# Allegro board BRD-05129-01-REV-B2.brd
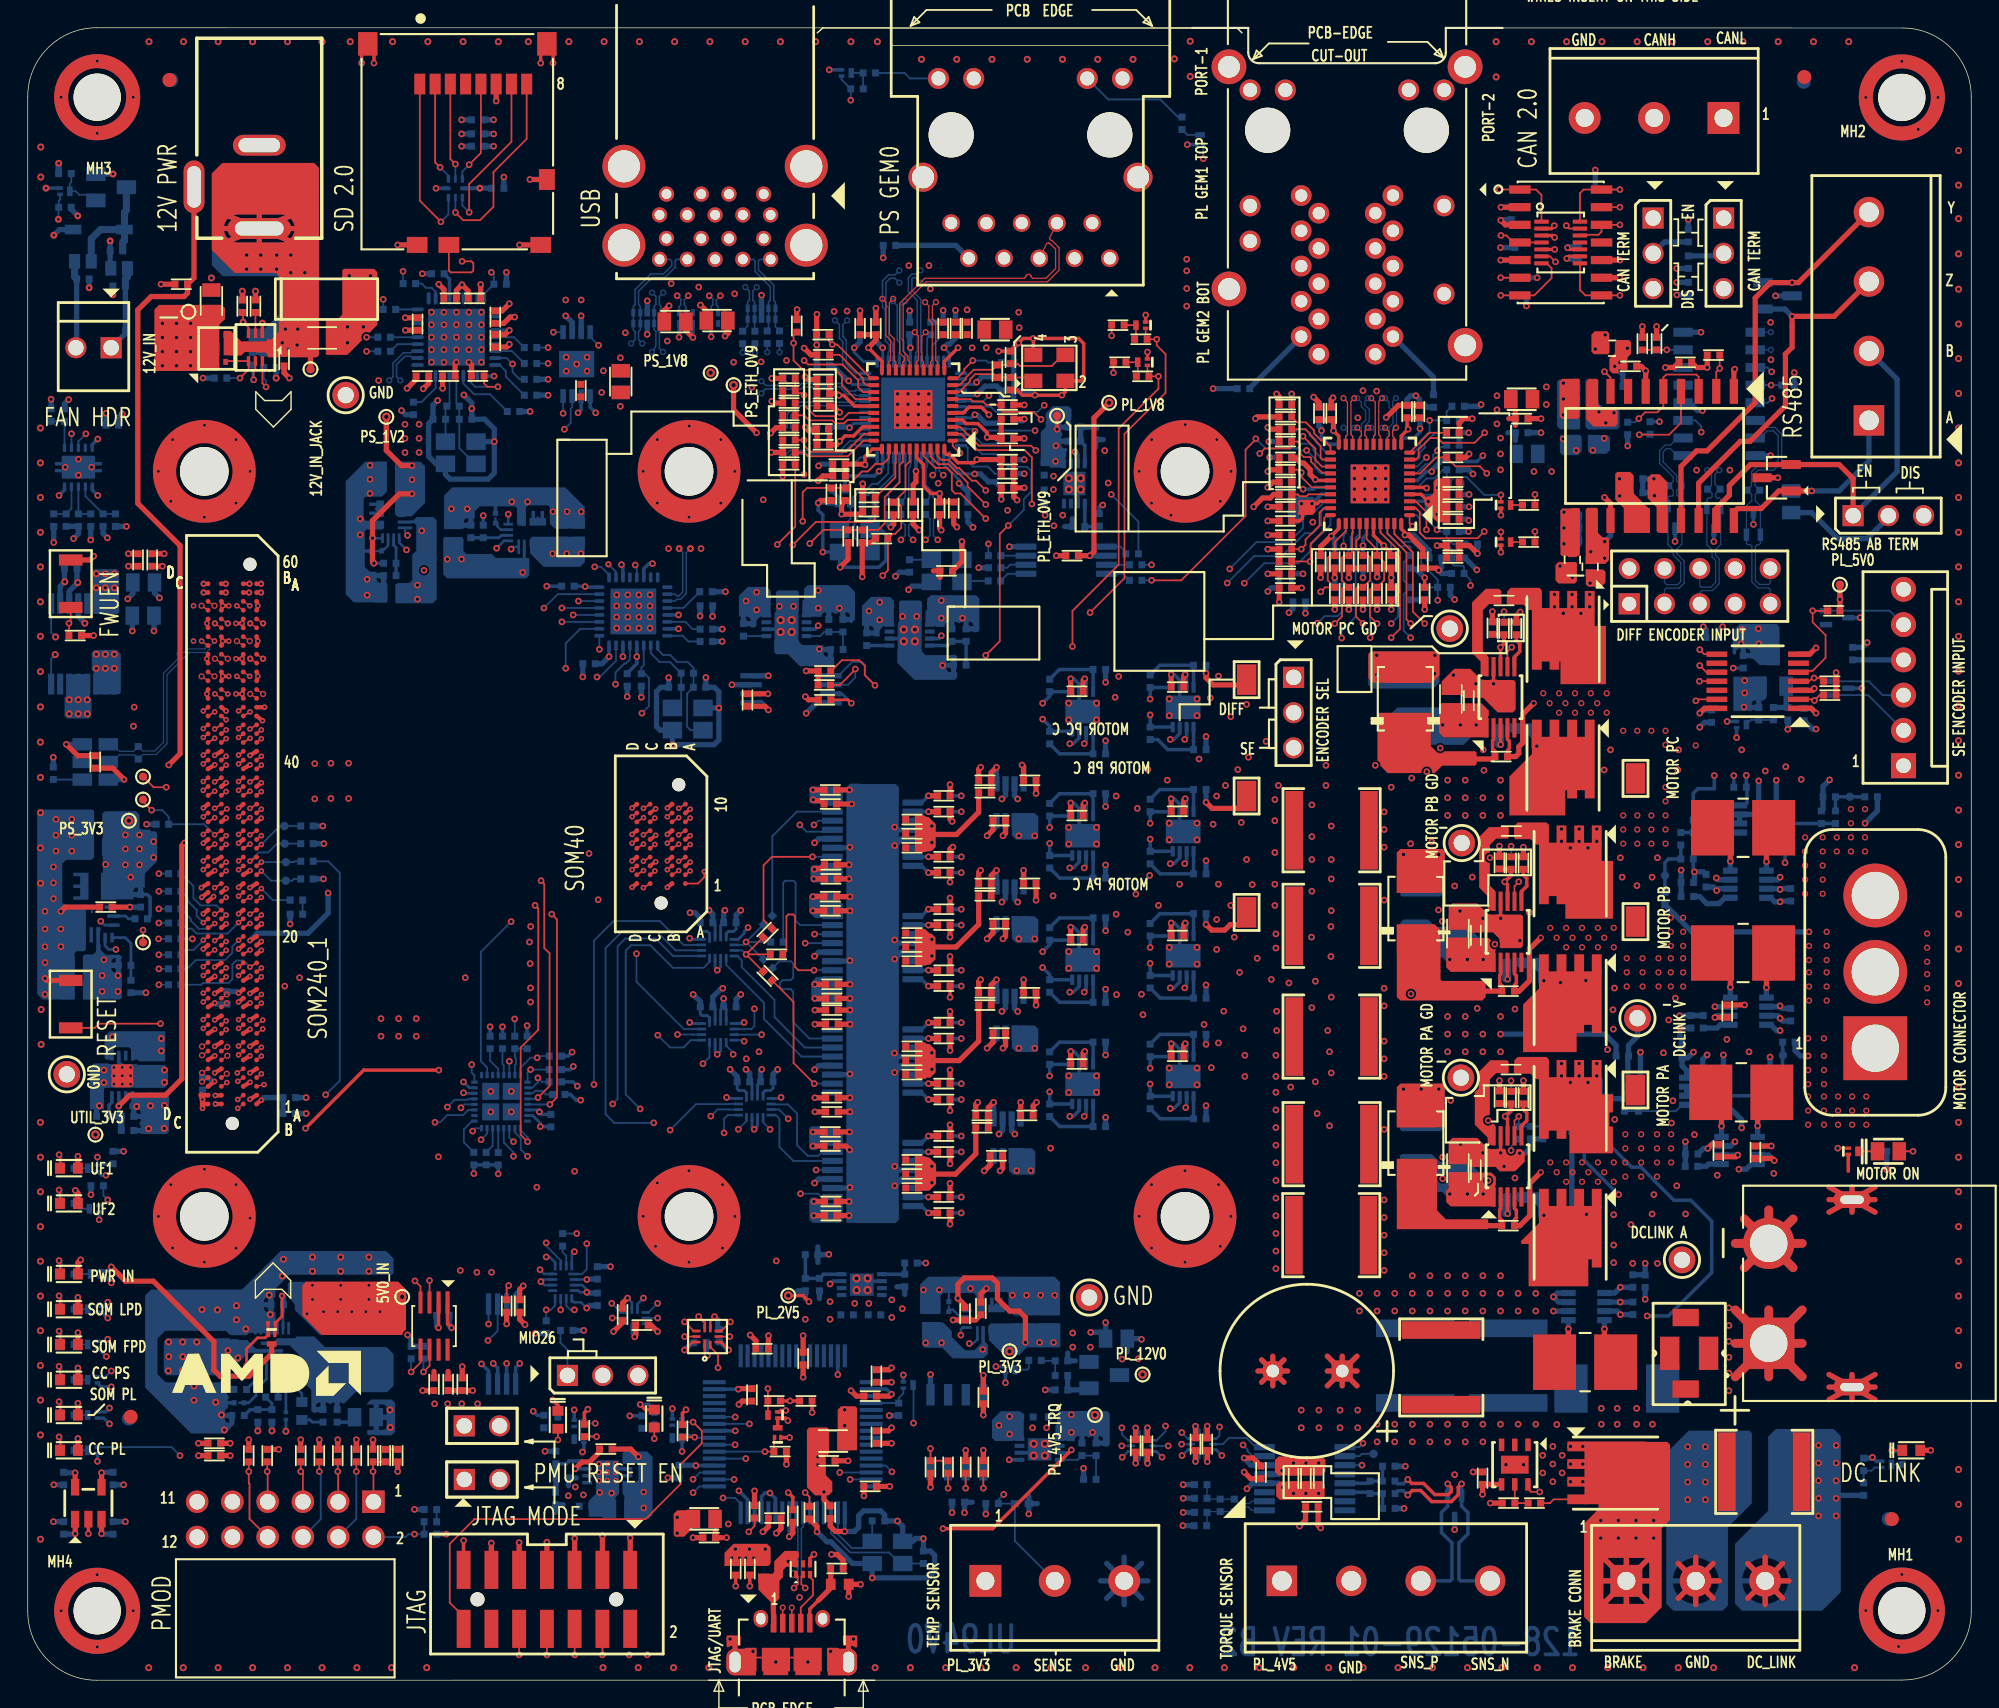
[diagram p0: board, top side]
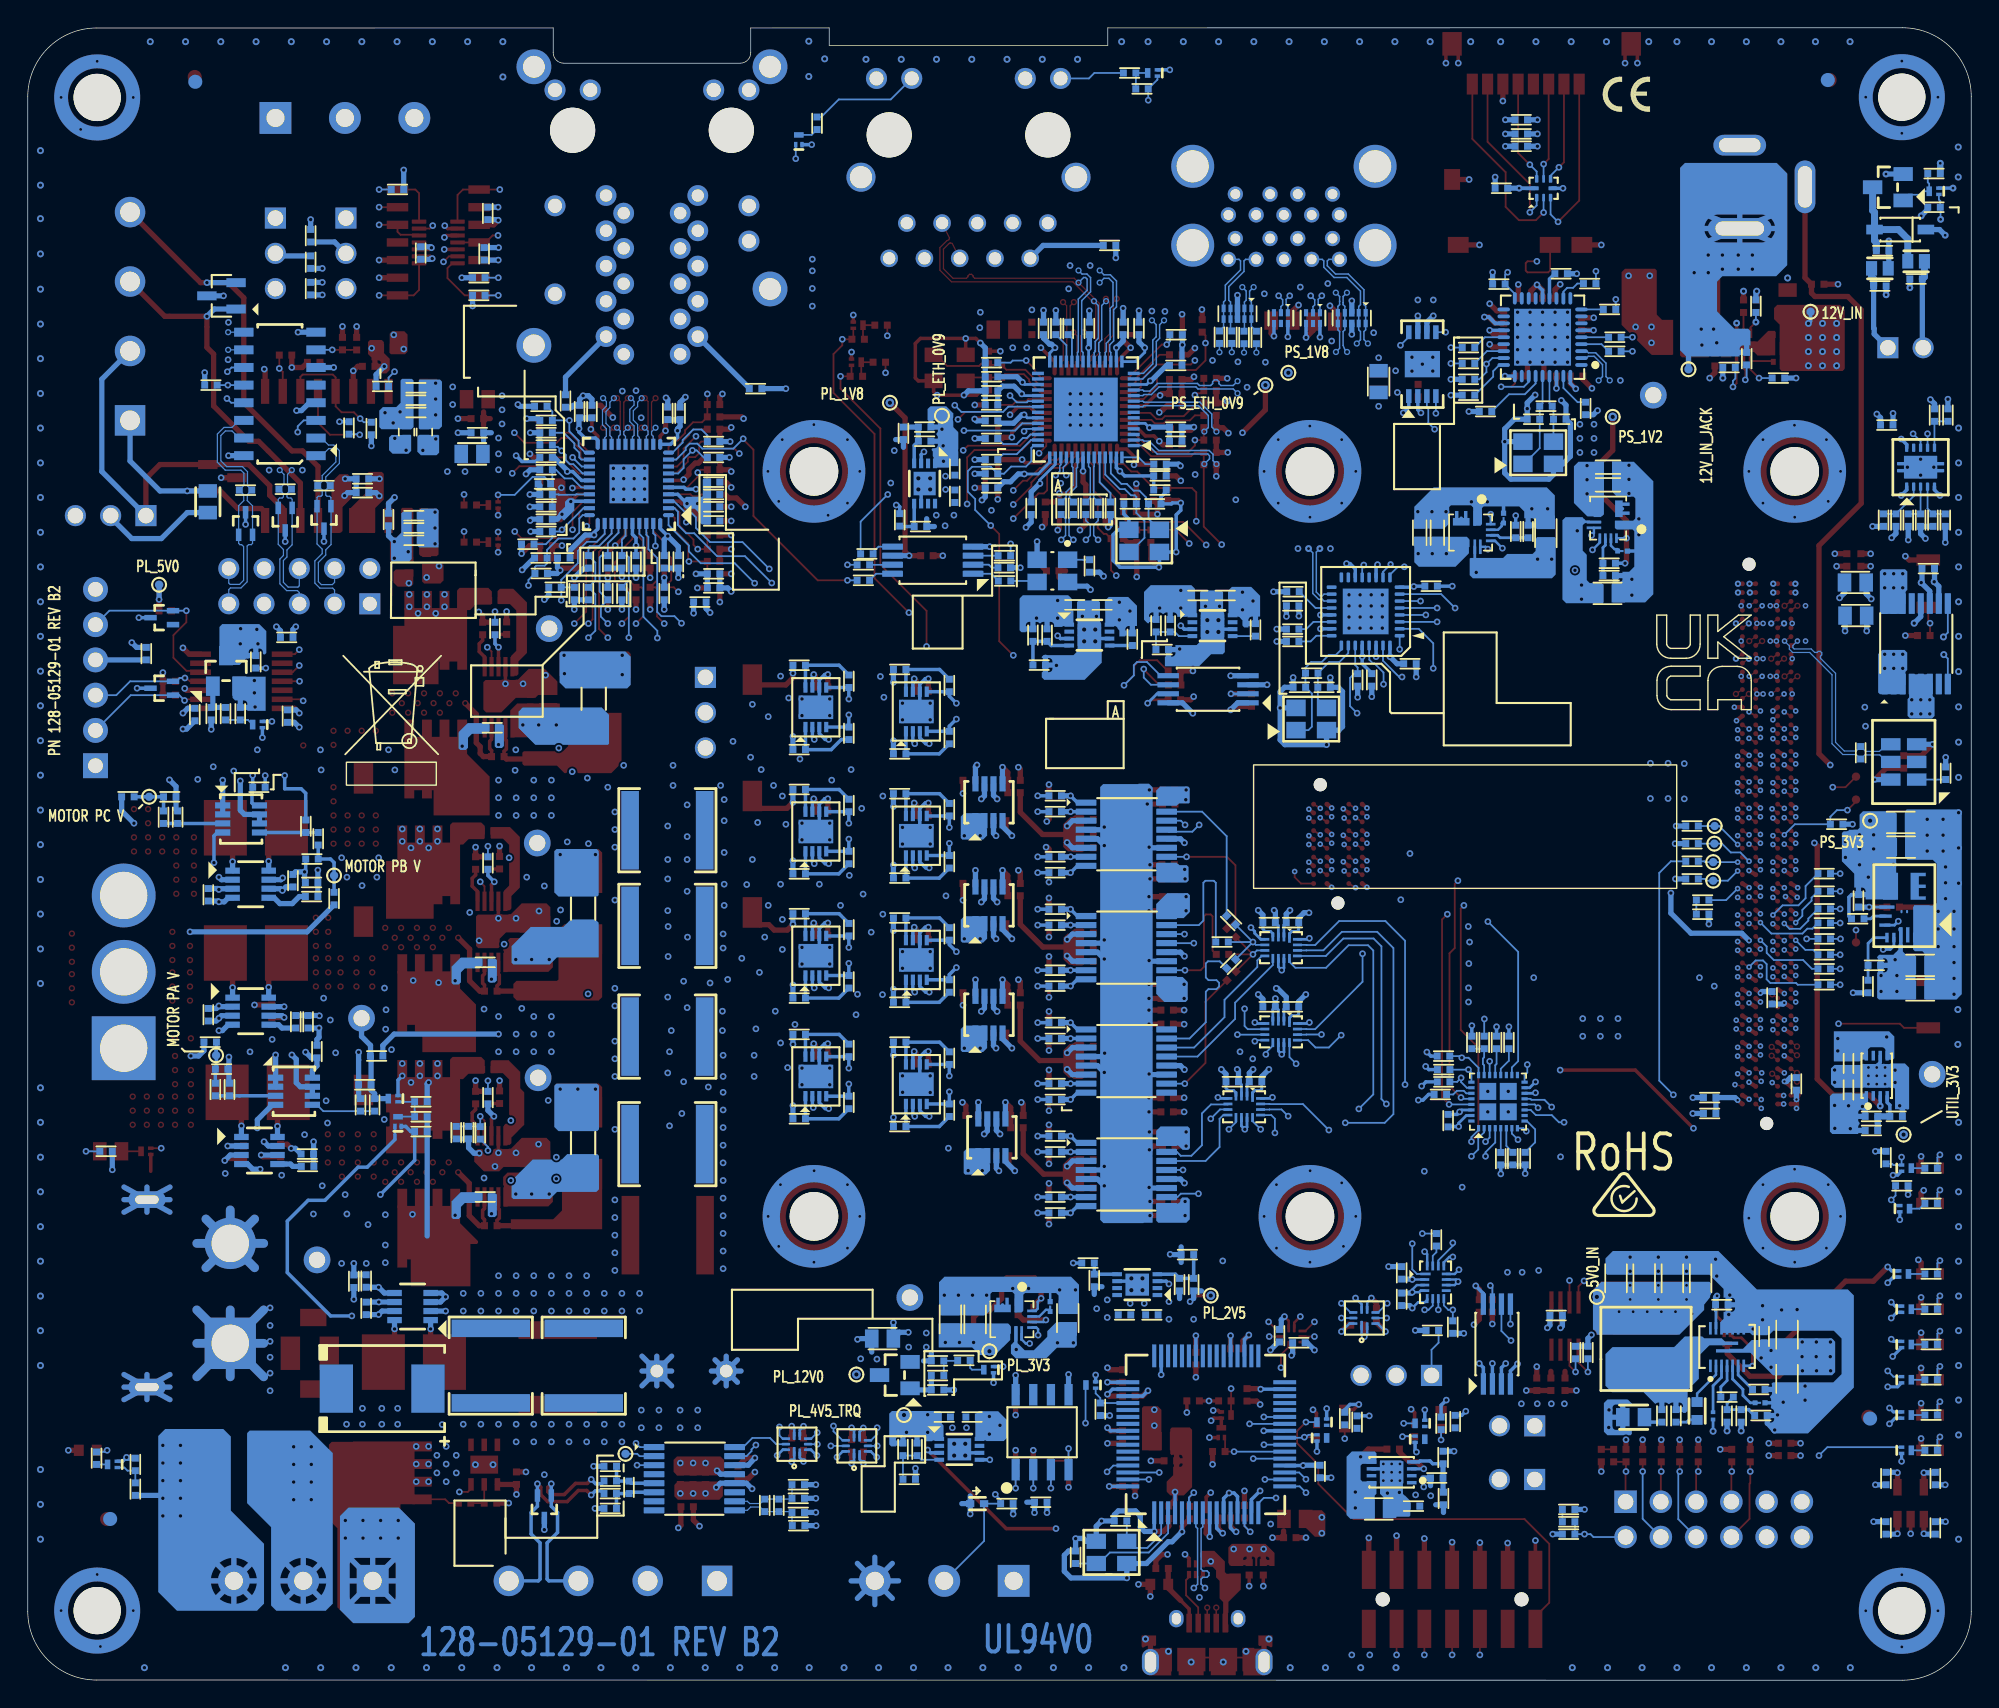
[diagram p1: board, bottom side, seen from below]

Outline 140 x 119 mm; copper layers: TOP, L02_GND, L03_SIG, L04_GND, L05_SIG, L06_GND, L07_PWR, L08_PWR, L09_GND, L10_SIG, L11_GND, L12_SIG, L13_GND, BOTTOM. Coordinates in mm from the lower left corner of the outline.
Outline path: 0,114.05 0,4.95 arc(1.45,1.45) 4.95,0 135.05,0.01 arc(138.55,1.47) 140,4.97 140,114.03 arc(138.55,117.53) 135.05,118.98 102.15,118.99 102.15,117.21 arc(101.93,116.67) 101.39,116.45 88.68,116.45 arc(88.14,116.67) 87.92,117.21 87.92,118.99 82.27,118.99 82.27,117.72 62.2,117.72 62.2,118.99 4.95,119 arc(1.45,117.55) 0,114.05

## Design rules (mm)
constraint set DEFAULT: min track width 0.13
net group 000-GTH_GTR_NC: nets GTR_DP1_C2M_N_NC GTR_DP1_C2M_P_NC
net group 23-PMOD_1-2_HD_SIGNALS: nets HDA08_CC HDA09_NC
net group GEM_SGMII_SO: nets GTR_DP0_C2M_N_NC GTR_DP0_C2M_P_NC
net group GTR_DP0_M2C_PAIR: nets GTR_DP0_M2C_N_NC GTR_DP0_M2C_P_NC
net group GTR_DP1_M2C_PAIR: nets GTR_DP1_M2C_N_NC GTR_DP1_M2C_P_NC
net group GTR_DP3_C2M: nets GTR_DP3_C2M_N_NC GTR_DP3_C2M_P_NC
net group GTR_DP3_M2C: nets GTR_DP3_M2C_N_NC GTR_DP3_M2C_P_NC
net group GTR_REFCLK0_C2M_PAIR: nets GTR_REFCLK0_C2M_N_NC GTR_REFCLK0_C2M_P_NC
net group GTR_REFCLK1_C2M_PAIR: nets GTR_REFCLK1_C2M_N_NC GTR_REFCLK1_C2M_P_NC
net group HDA12: nets HDA12 PMOD1_IO2_HDA12
net group HDA13: nets HDA13 PMOD1_IO3_HDA13
net group HDA14: nets HDA14 PMOD1_IO4_HDA14
net group HDA16_CC: nets HDA16_CC PMOD1_IO6_HDA16_CC
net group HDA17: nets HDA17 PMOD1_IO7_HDA17
net group HDA18: nets HDA18 PMOD1_IO8_HDA18
net group MG1_ETHERNET_GEM0_RGMII: nets MIO50 MIO51
net group MG7_MIO_RS485: nets MIO71 MIO72
net group MODE1_C2M: nets MODE1_C2M N15991161
net group N16080552: nets N16080552 N16080556
net group N16080656: nets N16080656 N16080660
net group N16080760: nets N16080760 N16080764
net group N16080864: nets N16080864 N16080868
net group N16080968: nets N16080968 N16080972
net group N16081072: nets N16081072 N16081076
net group N16082050: nets N16082024 N16082050
net group PL_GEM1_MDI_0: nets PL_GEM1_MDI_0_N PL_GEM1_MDI_0_P
net group PL_GEM1_MDI_1: nets PL_GEM1_MDI_1_N PL_GEM1_MDI_1_P
net group PL_GEM1_MDI_2: nets PL_GEM1_MDI_2_N PL_GEM1_MDI_2_P
net group PL_GEM1_MDI_3: nets PL_GEM1_MDI_3_N PL_GEM1_MDI_3_P
net group PL_GEM2_MDI_0: nets PL_GEM2_MDI_0_N PL_GEM2_MDI_0_P
net group PL_GEM2_MDI_1: nets PL_GEM2_MDI_1_N PL_GEM2_MDI_1_P
net group PL_GEM2_MDI_2: nets PL_GEM2_MDI_2_N PL_GEM2_MDI_2_P
net group PL_GEM2_MDI_3: nets PL_GEM2_MDI_3_N PL_GEM2_MDI_3_P
net group PS_GEM0_MDI_0: nets PS_GEM0_MDI_0_N PS_GEM0_MDI_0_P
net group PS_GEM0_MDI_1: nets PS_GEM0_MDI_1_N PS_GEM0_MDI_1_P
net group PS_GEM0_MDI_2: nets PS_GEM0_MDI_2_N PS_GEM0_MDI_2_P
net group PS_GEM0_MDI_3: nets PS_GEM0_MDI_3_N PS_GEM0_MDI_3_P
net group QEI_DP_A: nets QEI_DP_A_N QEI_DP_A_P
net group QEI_DP_B: nets QEI_DP_B_N QEI_DP_B_P
net group QEI_DP_I: nets QEI_DP_I_N QEI_DP_I_P
net group SDIO_CLK: nets SDIO_CLK SDIO_CLK_R
net group SDIO_CMD: nets SDIO_CMD SDIO_CMD_R
net group SDIO_DATA0: nets SDIO_DATA0 SDIO_DATA0_R
net group SDIO_DATA1: nets SDIO_DATA1 SDIO_DATA1_R
net group SDIO_DATA2: nets SDIO_DATA2 SDIO_DATA2_R
net group SDIO_DATA3: nets SDIO_DATA3 SDIO_DATA3_R
net group TRQ_REFIN: nets TRQ_REFIN_N TRQ_REFIN_P
net group TRQ_SNS: nets TRQ_SNS_N TRQ_SNS_P
net group TRQ_SNS_R: nets TRQ_SNS_R_N TRQ_SNS_R_P
net group 000-MIO_NC_SIGNALS: nets MIO32_NC MIO33_NC MIO34_NC
net group 1-SFP_HD_SIGNALS: nets HDA19_NC
net group 10-GEM2_HP_SIGNALS: nets HPA07P_CLK
net group 17-USB1_MIO_SIGNALS: nets MIO64_NC MIO65_NC MIO69_NC MIO73_NC MIO74_NC MIO75_NC
net group 22-DISPLAY_PORT_MIO: nets MIO27_NC MIO28_NC MIO29_NC MIO30_NC
net group 30-EEPROM_HD_SIGNALS: nets HDA01_NC
net group 33-PWR_GND: nets 5V0_IN_VCC 12V_FAN_GND 12V_FAN_PWR AGND1 AGND2 AGND3 AGND4 DCLINK_VOLT MOTOR_PA_VOLT MOTOR_PB_VOLT MOTOR_PB_VOLTAGE+ MOTOR_PB_VOLTAGE- MOTOR_PC_VOLT N5304511 N5322338 N5327477 N15992479 N15992497 N15992515 PL_4V5_TRQ PMOD_PWR_FLT_B VCC_BATT VCCOEN_PL_M2C VCCOEN_PS_M2C VREF_DCLINK VREF_PA VREF_PB VREF_PC
net group FTDI_NETS: nets FTDI_LS_OE_B FTDI_PS_POR_B FTDI_PS_SRST_B FTDI_TCK FTDI_TDI FTDI_TDO FTDI_TMS FTDI_UARTB_RXD FTDI_UARTB_TXD
net group GEM0_ETH_RX_RGMII_BUS: nets HPA09P HPA11P_CLK HPA_CLK0P_CLK
net group HDA11: nets HDA11
net group HDA15: nets HDA15
net group JTAG_TCK_C2M: nets JTAG_TCK_C2M N2549814 N16081750
net group JUNK: nets N3957555 N3957585 N3957595 N16082016 N16082026 N16082028 N16082060 N16082074 N16082098
net group MG2-ETHERNET_GEM1_RGMII: nets HPA05_CCN HPA05_CCP HPA06P HPA09N HPA10_CCN HPA10_CCP_CLK HPA_CLK0N
net group MG3-ETHERNET_GEM2_RGMII: nets HPA15_CCN HPA15_CCP HPA16N HPA16P_CLK HPA17N HPA18N HPA18P HPA19N HPA19P HPA20_CCP_CLK HPA22N HPA22P HPA24N HPA24P
net group MG5-SDIO_SIGNALS: nets SDIO_CD_B
net group MG6-USB0_MIO_SIGNALS: nets MIO52 MIO53 MIO54 MIO55 MIO56 MIO57 MIO58 MIO59 MIO60 MIO61 MIO62 MIO63
net group MG_MIO_CAN2.0: nets MIO66 MIO67 MIO68
net group MOTOR_PA_CS_B: nets MOTOR_CS_B_R MOTOR_PA_CS_B MOTOR_PB_CS_B MOTOR_PC_CS_B
net group MOTOR_PA_SCLK: nets MOTOR_PA_SCLK MOTOR_PB_SCLK MOTOR_PC_SCLK MOTOR_SCLK_R
net group PL_2V5_FB: nets PL_2V5_FB
net group POWER: nets N16081820
net group SDIO_CARD_BUS: nets SDIO_SCK SDIO_SDA SDIO_WP
net group USB_JTAG_VBUS: nets N16081954
net group WATCHDOG_NETS: nets WATCHDOG_CRST WATCHDOG_CWD WATCHDOG_SET0 WATCHDOG_SET1 WATCHDOG_WDO_B

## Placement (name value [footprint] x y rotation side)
C1  22UF  [CAPC200X125X145]  5.05 60 180 bottom
C2  22UF  [CAPC200X125X145]  5.08 61.77 180 bottom
C3  22UF  [CAPC200X125X145]  3.68 51.48 180 bottom
C4  47UF  [CAPC200X125X125]  3.68 49.7 180 bottom
C5  27PF  [CAPC100X50X55]  8.17 54.83 180 bottom
C6  22UF  [CAPC200X125X145]  30.64 82.6 90 bottom
C7  22UF  [CAPC160X80X100]  39.73 82.64 90 bottom
C8  22UF  [CAPC160X80X100]  38.46 82.64 90 bottom
C14  1000PF  [CAPC100X50X55]  66.58 75.26 270 bottom
C16  10UF  [CAPC100X50X70]  64.58 77.44 180 bottom
C17  10UF  [CAPC100X50X70]  62.61 77.44 0 bottom
C21  1000PF  [CAPC100X50X55]  57.03 28.49 90 bottom
C22  10UF  [CAPC100X50X70]  59.03 26.31 0 bottom
C23  10UF  [CAPC100X50X70]  61 26.31 180 bottom
C24  22UF  [CAPC160X80X100]  26.17 86.09 180 bottom
C25  22UF  [CAPC160X80X100]  26.17 87.36 180 bottom
C26  22UF  [CAPC200X125X145]  26.2 78.27 180 bottom
C27  1000PF  [CAPC100X50X55]  75.4 89.23 0 bottom
C28  10UF  [CAPC100X50X70]  73.22 87.23 270 bottom
C29  10UF  [CAPC100X50X70]  73.22 85.26 90 bottom
C30  22UF  [CAPC200X125X145]  13.27 21.71 270 bottom
C31  22UF  [CAPC200X125X145]  13.27 24.88 90 bottom
C32  22UF  [CAPC200X125X145]  21.53 28.94 90 bottom
C33  22UF  [CAPC200X125X145]  23.56 28.94 90 bottom
C34  22UF  [CAPC200X125X145]  19.49 28.94 90 bottom
C35  22UF  [CAPC200X125X145]  25.59 28.94 90 bottom
C36  0.1UF  [CAPC100X50X55]  14.92 24.75 90 bottom
C37  0.1UF  [CAPC100X50X55]  21.27 19.04 90 bottom
C38  1UF  [CAPC100X50X70]  17.97 27.04 180 bottom
C39  56PF  [CAPC100X50X55]  17.59 19.04 90 bottom
C40  0.022uF  [CAPC100X50X55]  15.3 20.94 180 bottom
C41  1000PF  [CAPC100X50X55]  7.19 40.61 180 bottom
C42  10UF  [CAPC100X50X70]  8.84 42.51 90 bottom
C43  10UF  [CAPC100X50X70]  8.84 44.42 270 bottom
C44  1000PF  [CAPC100X50X55]  38.02 13.09 90 bottom
C49  0.1UF  [CAPC100X50X55]  3.09 80.06 0 bottom
C50  0.1UF  [CAPC100X50X55]  6.08 90.39 0 bottom
C51  1UF  [CAPC100X50X70]  6.32 83.54 270 bottom
C52  0.22UF  [CAPC100X50X55]  1.87 83.54 270 bottom
C53  0.1UF  [CAPC100X50X55]  35.44 26.95 270 top
C64  0.1UF  [CAPC100X50X55]  31.3 21.31 270 top
C73  100PF  [CAPC100X50X55]  30.28 21.31 270 top
C75  0.1UF  [CAPC100X50X55]  37.68 40.3 90 bottom
C78  10uF  [CAPC200X125X145]  42.68 12.33 180 bottom
C79  10UF  [CAPC100X50X70]  40.18 12.54 0 bottom
C80  0.1UF  [CAPC100X50X55]  41.03 27.43 270 bottom
C81  0.1UF  [CAPC100X50X55]  41.03 29.34 90 bottom
C82  4.7UF  [CAPC100X50X60]  57.69 15.8 0 top
C83  0.1UF  [CAPC100X50X55]  57.81 12.09 270 top
C84  0.1UF  [CAPC100X50X55]  55.11 11.82 90 top
C85  4.7UF  [CAPC100X50X60]  49.09 10.27 180 top
C87  0.1UF  [CAPC100X50X55]  52.02 8.02 270 top
C88  0.1UF  [CAPC100X50X55]  58.29 8.05 180 top
C89  1UF  [CAPC100X50X70]  51 8.02 270 top
C90  0.1UF  [CAPC100X50X55]  48.43 24.3 0 bottom
C91  0.1UF  [CAPC100X50X55]  49.83 24.81 270 bottom
C92  0.1UF  [CAPC100X50X55]  42.85 26.34 270 top
C93  0.1UF  [CAPC100X50X55]  44.24 25.57 180 top
C94  0.1UF  [CAPC100X50X55]  68.84 20.36 270 top
C95  4.7UF  [CAPC100X50X60]  61.14 21.91 90 top
C96  0.1UF  [CAPC100X50X55]  53.81 11.68 0 top
C97  0.1UF  [CAPC100X50X55]  60.69 13.96 180 top
C98  0.1UF  [CAPC100X50X55]  52.91 23.87 180 top
C99  0.1UF  [CAPC100X50X55]  55.86 23.16 270 top
C100  0.1UF  [CAPC100X50X55]  61.14 17.51 270 top
C101  0.1UF  [CAPC100X50X55]  52.17 20.55 270 top
C102  0.1UF  [CAPC100X50X55]  46.91 15.03 270 bottom
C103  27PF  [CAPC100X50X55]  61.28 11.47 0 bottom
C104  27PF  [CAPC100X50X55]  64.52 8.85 90 bottom
C105  0.1UF  [CAPC100X50X55]  60.69 20.46 180 top
C175  1UF  [CAPC100X50X70]  29.54 101.29 180 bottom
C176  0.1UF  [CAPC100X50X55]  30.43 99.51 180 top
C203  10uF  [CAPC200X125X145]  13.23 99.33 90 top
C204  10uF  [CAPC200X125X145]  21.21 96.66 0 top
C205  1UF  [CAPC100X50X70]  18.47 95.1 270 top
C206  0.047UF  [CAPC100X50X50]  17.45 94.53 0 bottom
C207  0.1UF  [CAPC100X50X55]  11.06 100.53 180 top
C208  1UF  [CAPC100X50X70]  6.39 102.94 0 bottom
C209  0.1UF  [CAPC100X50X55]  3.97 100.91 0 bottom
C210  0.1UF  [CAPC100X50X55]  6.58 100.4 180 bottom
C234  0.1UF  [CAPC100X50X55]  13.89 93.77 180 bottom
C235  39PF  [CAPC100X50X55]  15.45 98.95 90 top
C236  0.1UF  [CAPC100X50X55]  3.42 75.23 0 top
C237  0.1UF  [CAPC100X50X55]  2.59 14.52 270 bottom
C238  1UF  [CAPC100X50X70]  13.44 17.06 0 top
C272  22UF  [CAPC200X125X145]  49.65 97.91 0 top
C273  0.1UF  [CAPC100X50X55]  48.88 77.37 0 bottom
C274  22UF  [CAPC200X125X145]  46.63 97.84 0 top
C275  0.1UF  [CAPC100X50X55]  38.91 78.79 180 bottom
C276  0.1UF  [CAPC100X50X55]  40.43 73.2 180 bottom
C277  0.1UF  [CAPC100X50X55]  43.18 72.04 270 bottom
C278  2.2UF  [CAPC100X50X55]  48.86 78.39 180 bottom
C279  0.1UF  [CAPC100X50X55]  51.5 96.7 90 bottom
C280  0.1UF  [CAPC100X50X55]  53.27 96.72 270 bottom
C281  0.1UF  [CAPC100X50X55]  52.39 96.7 90 bottom
C282  0.1UF  [CAPC100X50X55]  54.16 96.72 270 bottom
C283  0.1UF  [CAPC100X50X55]  59.95 97.35 90 bottom
C284  0.1UF  [CAPC100X50X55]  57.31 89.22 180 bottom
C285  0.1UF  [CAPC100X50X55]  63.78 84.4 270 top
C286  0.1UF  [CAPC100X50X55]  57.31 94.69 180 bottom
C289  0.1UF  [CAPC100X50X55]  66.83 97.35 90 bottom
C290  0.1UF  [CAPC100X50X55]  70.58 85.87 0 bottom
C291  0.1UF  [CAPC100X50X55]  70.58 91.84 0 bottom
C292  0.1UF  [CAPC100X50X55]  63.53 97.35 90 bottom
C295  1000PF  [CAPC100X50X55]  57.31 90.24 180 bottom
C296  1000PF  [CAPC100X50X55]  70.58 92.85 0 bottom
C297  1000PF  [CAPC100X50X55]  61.1 97.35 90 bottom
C298  1000PF  [CAPC100X50X55]  58.44 86.73 180 bottom
C299  0.1UF  [CAPC100X50X55]  67.72 84.4 270 bottom
C300  0.1UF  [CAPC100X50X55]  70.58 90.69 0 bottom
C303  0.1UF  [CAPC100X50X55]  58.44 85.71 180 bottom
C304  0.1UF  [CAPC100X50X55]  70.58 93.87 0 bottom
C309  0.1UF  [CAPC100X50X55]  64.67 84.4 90 bottom
C310  0.1UF  [CAPC100X50X55]  65.56 84.4 90 bottom
C311  22UF  [CAPC200X125X145]  42.72 93.52 90 top
C312  22UF  [CAPC200X125X145]  42.69 93.52 90 bottom
C315  0.1UF  [CAPC100X50X55]  62.89 84.4 90 bottom
C316  0.1UF  [CAPC100X50X55]  63.78 84.4 90 bottom
C317  0.1UF  [CAPC100X50X55]  39.85 92.87 90 top
C319  6800PF  [CAPC100X50X70]  22.29 19.04 270 bottom
C323  1UF  [CAPC100X50X70]  8.96 80.67 90 top
C324  0.1UF  [CAPC100X50X55]  7.95 80.67 90 top
C329  0.1UF  [CAPC100X50X55]  29.9 26.27 0 bottom
C344  33PF  [CAPC100X50X56]  19.35 55.16 180 bottom
C353  47UF  [CAPC200X125X125]  8.31 76.66 180 bottom
C354  47UF  [CAPC200X125X125]  8.35 79.05 180 bottom
C369  0.1UF  [CAPC100X50X55]  32.41 112.37 0 bottom
C370  33PF  [CAPC100X50X56]  26.65 16.18 270 top
C371  33PF  [CAPC100X50X56]  29 12.3 180 bottom
C372  10PF  [CAPC100X50X55]  24.87 16.18 90 top
C373  10PF  [CAPC100X50X55]  29 10.52 0 bottom
C374  10PF  [CAPC100X50X55]  22.33 16.18 90 top
C375  10PF  [CAPC100X50X55]  23.67 16.18 90 top
C376  10PF  [CAPC100X50X55]  13.44 16.18 0 top
C377  10PF  [CAPC100X50X55]  19.66 16.18 90 top
C378  10PF  [CAPC100X50X55]  21 16.18 90 top
C379  10PF  [CAPC100X50X55]  17.25 16.18 90 top
C380  10PF  [CAPC100X50X55]  15.92 16.18 90 top
C387  10UF  [CAPC100X50X70]  2.59 10.97 90 bottom
C548  0.1UF  [CAPC100X50X55]  35.97 45.93 90 bottom
C557  4.7UF  [CAPC100X50X60]  32.41 111.35 0 bottom
C558  1000PF  [CAPC100X50X55]  33.68 98.16 90 top
C559  0.1UF  [CAPC100X50X55]  28.08 97.66 90 top
C560  0.1UF  [CAPC100X50X55]  33.68 96.46 270 top
C561  0.1UF  [CAPC100X50X55]  28.43 93.91 180 top
C562  1UF  [CAPC100X50X70]  30.33 93.91 0 top
C563  27PF  [CAPC100X50X55]  29.64 90.81 180 bottom
C564  27PF  [CAPC100X50X55]  31.53 90.81 0 bottom
C565  0.1UF  [CAPC100X50X55]  33.85 107.44 0 bottom
C566  18PF  [CAPC100X50X50]  46.62 71.5 180 bottom
C567  18PF  [CAPC100X50X50]  48.4 71.5 0 bottom
C568  27PF  [CAPC100X50X55]  58.82 84.71 180 bottom
C569  27PF  [CAPC100X50X55]  60.6 84.71 0 bottom
C574  4.7UF  [CAPC100X50X60]  32.18 99.51 0 top
C581  1UF  [CAPC100X50X70]  14.35 49.14 270 bottom
C582  1UF  [CAPC100X50X70]  12.59 42.95 90 bottom
C589  0.1UF  [CAPC100X50X55]  4.86 66.13 90 top
C591  0.1UF  [CAPC100X50X55]  75.23 80.98 180 top
C592  0.1UF  [CAPC100X50X55]  66.17 79.89 0 top
C598  0.1UF  [CAPC100X50X55]  111.7 102.78 270 bottom
C599  0.1UF  [CAPC100X50X55]  106.86 105.63 90 bottom
C600  0.1UF  [CAPC100X50X55]  107.13 102.72 90 bottom
C601  4700PF  [CAPC100X50X55]  119.62 100.21 270 bottom
C602  0.1UF  [CAPC100X50X55]  115.45 94.62 0 top
C603  0.1UF  [CAPC100X50X55]  115.89 86.52 180 bottom
C604  10UF  [CAPC100X50X70]  115.89 85.52 180 bottom
C605  10UF  [CAPC100X50X70]  112.04 91.29 180 bottom
C606  1UF  [CAPC100X50X70]  112.04 92.18 180 bottom
C607  0.01uF  [CAPC100X50X55]  112.04 93.07 180 bottom
C608  0.01uF  [CAPC100X50X55]  112.19 83.87 180 bottom
C609  1UF  [CAPC100X50X70]  112.19 82.09 180 bottom
C610  10UF  [CAPC100X50X70]  112.19 82.98 180 bottom
C611  10UF  [CAPC100X50X70]  53.74 78.12 0 bottom
C612  1000PF  [CAPC100X50X55]  57.71 75.94 270 bottom
C613  10UF  [CAPC100X50X70]  55.71 78.12 180 bottom
C614  22UF  [CAPC200X125X145]  73.54 25.99 90 bottom
C615  22UF  [CAPC200X125X145]  71.76 25.99 90 bottom
C616  22UF  [CAPC200X125X145]  65.08 26.08 90 bottom
C617  10uF  [CAPC200X125X145]  78.43 24.6 180 bottom
C618  10UF  [CAPC100X50X70]  123.58 73.34 270 bottom
C619  0.1UF  [CAPC100X50X55]  74.46 20.91 180 bottom
C620  0.1UF  [CAPC100X50X55]  126.79 69.6 270 bottom
C621  0.1UF  [CAPC100X50X55]  18.84 41.96 0 bottom
C622  0.1UF  [CAPC100X50X55]  70.58 86.88 0 top
C623  0.1UF  [CAPC100X50X55]  57.31 93.67 180 top
C624  0.1UF  [CAPC100X50X55]  70.58 87.9 0 top
C625  0.01uF  [CAPC100X50X55]  59.95 97.35 90 top
C626  0.01uF  [CAPC100X50X55]  65.94 97.35 90 top
C627  0.1UF  [CAPC100X50X55]  70.58 89.42 0 top
C628  0.1UF  [CAPC100X50X55]  57.23 90.11 180 top
C629  0.1UF  [CAPC100X50X55]  57.31 91.76 180 top
C630  10UF  [CAPC100X50X70]  65.69 84.4 270 top
C631  0.01uF  [CAPC100X50X55]  70.58 85.87 0 top
C632  0.01uF  [CAPC100X50X55]  58.44 86.73 180 top
C633  10UF  [CAPC100X50X70]  58.44 87.57 180 top
C634  0.1UF  [CAPC100X50X55]  66.83 97.35 90 top
C635  0.1UF  [CAPC100X50X55]  61.1 97.35 90 top
C636  0.01uF  [CAPC100X50X55]  57.31 88.97 180 top
C637  0.01uF  [CAPC100X50X55]  70.58 90.82 0 top
C638  0.01uF  [CAPC100X50X55]  66.7 84.4 270 top
C640  0.01uF  [CAPC100X50X55]  57.31 92.65 180 top
C641  10UF  [CAPC100X50X70]  67.67 97.35 90 top
C642  0.1UF  [CAPC100X50X55]  62.07 103.33 180 bottom
C643  18PF  [CAPC100X50X50]  70.79 93.37 270 top
C644  18PF  [CAPC100X50X50]  70.79 95.26 90 top
C645  0.1UF  [CAPC100X50X55]  102.66 80.82 0 top
C646  0.1UF  [CAPC100X50X55]  101.39 80.82 0 bottom
C647  0.1UF  [CAPC100X50X55]  94.15 78.25 270 bottom
C648  0.01uF  [CAPC100X50X55]  99.36 91.36 90 bottom
C649  0.01uF  [CAPC100X50X55]  93.9 91.23 90 bottom
C650  0.1UF  [CAPC100X50X55]  96.19 80.54 270 bottom
C651  0.1UF  [CAPC100X50X55]  90.6 84.5 180 bottom
C652  0.1UF  [CAPC100X50X55]  90.6 83.49 180 bottom
C653  10UF  [CAPC100X50X70]  90.6 86.28 180 bottom
C654  0.01uF  [CAPC100X50X55]  94.15 80.54 270 bottom
C655  0.01uF  [CAPC100X50X55]  93.14 80.54 270 bottom
C656  0.01uF  [CAPC100X50X55]  102.66 88.06 0 bottom
C657  10UF  [CAPC100X50X70]  102.66 81.71 0 top
C658  0.1UF  [CAPC100X50X55]  100.25 91.36 90 bottom
C659  0.1UF  [CAPC100X50X55]  93.01 91.23 90 bottom
C660  10UF  [CAPC100X50X70]  107.62 89.84 0 bottom
C661  0.01uF  [CAPC100X50X55]  91.59 77.64 180 bottom
C662  0.01uF  [CAPC100X50X55]  102.66 83.61 0 bottom
C663  0.01uF  [CAPC100X50X55]  90.6 85.39 180 bottom
C665  0.1UF  [CAPC100X50X55]  87.58 93.01 180 bottom
C666  0.1UF  [CAPC100X50X55]  51.85 70.59 270 top
C667  0.1UF  [CAPC100X50X55]  100.63 78.25 270 top
C668  0.1UF  [CAPC100X50X55]  90.6 78.66 0 top
C669  0.1UF  [CAPC100X50X55]  90.6 78.66 180 bottom
C670  0.01uF  [CAPC100X50X55]  93.9 91.23 90 top
C671  0.01uF  [CAPC100X50X55]  93.01 91.23 90 top
C672  0.1UF  [CAPC100X50X55]  98.22 80.54 270 top
C673  0.1UF  [CAPC100X50X55]  102.66 83.61 0 top
C674  0.1UF  [CAPC100X50X55]  102.66 84.5 0 top
C675  10UF  [CAPC100X50X70]  102.66 86.28 0 top
C676  0.01uF  [CAPC100X50X55]  93.14 80.54 270 top
C677  0.01uF  [CAPC100X50X55]  90.6 88.06 180 top
C678  0.01uF  [CAPC100X50X55]  90.6 79.68 180 bottom
C679  10UF  [CAPC100X50X70]  100.5 80.54 270 top
C680  0.1UF  [CAPC100X50X55]  99.36 91.36 90 top
C681  0.1UF  [CAPC100X50X55]  100.25 91.36 90 top
C682  10UF  [CAPC100X50X70]  107.62 90.85 0 top
C683  0.01uF  [CAPC100X50X55]  98.22 78.25 90 top
C684  0.01uF  [CAPC100X50X55]  90.6 83.49 180 top
C685  0.01uF  [CAPC100X50X55]  102.66 85.39 0 top
C687  0.1UF  [CAPC100X50X55]  101.27 92.12 270 bottom
C688  0.22UF  [CAPC100X50X55]  106.65 32.73 0 top
C689  10UF  [CAPC620X540X280]  93.93 38.6 180 bottom
C690  10UF  [CAPC620X540X280]  93.9 32.05 180 top
C691  10UF  [CAPC620X540X280]  93.93 38.6 180 top
C692  10uF  [CAPC200X125X145]  103.02 53.77 90 top
C693  0.1UF  [CAPC100X50X55]  104.31 53.64 90 top
C694  0.1UF  [CAPC100X50X55]  109.14 39.43 270 bottom
C695  0.1UF  [CAPC100X50X55]  106.02 41.98 90 top
C696  0.22UF  [CAPC100X50X55]  106.65 49.62 0 top
C697  10UF  [CAPC620X540X280]  93.93 46.35 180 top
C698  10UF  [CAPC620X540X280]  93.93 46.35 180 bottom
C699  10UF  [CAPC620X540X280]  93.93 54.33 180 top
C700  10uF  [CAPC200X125X145]  103.02 36.88 90 top
C701  0.1UF  [CAPC100X50X55]  104.31 36.75 90 top
C702  0.1UF  [CAPC100X50X55]  106.02 58.87 90 top
C703  0.22UF  [CAPC100X50X55]  106.14 66.51 0 top
C704  10UF  [CAPC620X540X280]  93.93 61.21 180 bottom
C705  10UF  [CAPC620X540X280]  93.93 54.33 180 bottom
C706  10UF  [CAPC620X540X280]  93.93 61.21 180 top
C707  10uF  [CAPC200X125X145]  102.51 70.66 90 top
C708  0.1UF  [CAPC100X50X55]  103.81 70.53 90 top
C709  0.1UF  [CAPC100X50X55]  105.51 75.76 90 top
C710  0.1UF  [CAPC100X50X55]  121.79 38.15 90 top
C711  0.1UF  [CAPC100X50X55]  124.46 38.02 90 top
C712  0.1UF  [CAPC100X50X55]  122.42 48.18 90 top
C713  0.1UF  [CAPC100X50X55]  127 47.93 90 bottom
C714  0.1UF  [CAPC100X50X55]  120.9 57.58 90 bottom
C715  0.1UF  [CAPC100X50X55]  127 56.56 270 bottom
C716  10UF  [CAPC100X50X70]  57.92 40.93 0 top
C717  0.1UF  [CAPC100X50X55]  57.92 41.95 0 top
C718  0.1UF  [CAPC100X50X55]  50.58 54.56 0 bottom
C719  0.1UF  [CAPC100X50X55]  48.9 54.56 180 bottom
C720  0.1UF  [CAPC100X50X55]  57.92 47.24 0 top
C721  10UF  [CAPC100X50X70]  57.92 48.26 0 top
C722  100PF  [CAPC100X50X55]  125.47 42.54 90 bottom
C723  2700PF  [CAPC100X50X55]  119.86 37.89 0 bottom
C724  10UF  [CAPC100X50X70]  63.7 43.61 180 top
C725  0.1UF  [CAPC100X50X55]  63.7 45.64 180 top
C726  0.1UF  [CAPC100X50X55]  63.7 44.63 180 top
C727  10UF  [CAPC100X50X70]  57.92 49.1 0 top
C728  0.1UF  [CAPC100X50X55]  57.92 50.11 0 top
C729  0.1UF  [CAPC100X50X55]  57.81 55.41 0 top
C730  10UF  [CAPC100X50X70]  57.81 56.43 0 top
C731  100PF  [CAPC100X50X55]  119.97 61.5 90 bottom
C732  0.1UF  [CAPC100X50X55]  50.58 48.49 0 bottom
C733  0.1UF  [CAPC100X50X55]  48.9 48.49 180 bottom
C734  2700PF  [CAPC100X50X55]  119.81 47.42 270 bottom
C735  10UF  [CAPC100X50X70]  63.7 51.78 180 top
C736  0.1UF  [CAPC100X50X55]  63.7 53.81 180 top
C737  0.1UF  [CAPC100X50X55]  63.7 52.8 180 top
C738  0.1UF  [CAPC100X50X55]  57.81 63.1 0 top
C739  10UF  [CAPC100X50X70]  57.81 64.11 0 top
C740  10UF  [CAPC100X50X70]  57.85 57.71 0 top
C741  0.1UF  [CAPC100X50X55]  57.85 58.72 0 top
C742  100PF  [CAPC100X50X55]  129.21 62.15 90 bottom
C743  2700PF  [CAPC100X50X55]  119.55 57.45 0 bottom
C744  10UF  [CAPC100X50X70]  63.7 59.95 180 top
C745  0.1UF  [CAPC100X50X55]  63.7 60.96 180 top
C746  0.1UF  [CAPC100X50X55]  63.7 61.98 180 top
C747  0.1UF  [CAPC100X50X55]  115.63 26.78 270 bottom
C748  10UF  [CAPC620X540X280]  99.95 22.65 270 bottom
C749  10UF  [CAPC620X540X280]  101.82 22.53 270 top
C750  10UF  [CAPC620X540X280]  106.65 22.66 270 bottom
C751  470 uF  [CAPE_1250X2000]  94.69 22.27 180 top
C752  10UF  [CAPC100X50X70]  57.85 33.46 0 top
C753  0.1UF  [CAPC100X50X55]  57.85 34.48 0 top
C754  0.1UF  [CAPC100X50X55]  53.24 43.1 0 bottom
C755  0.1UF  [CAPC100X50X55]  51.56 43.1 180 bottom
C756  0.1UF  [CAPC100X50X55]  57.81 38.47 0 top
C757  10UF  [CAPC100X50X70]  57.81 39.48 0 top
C758  1000PF  [CAPC100X50X55]  116.03 41.43 90 bottom
C759  0.068UF  [CAPC100X50X55]  116.51 28.73 270 bottom
C760  10UF  [CAPC100X50X70]  63.7 35.44 180 top
C761  0.1UF  [CAPC100X50X55]  63.7 36.46 180 top
C762  0.1UF  [CAPC100X50X55]  63.7 37.48 180 top
C763  0.1UF  [CAPC100X50X55]  127.97 69.54 270 bottom
C764  0.1UF  [CAPC100X50X55]  121.29 69.43 270 bottom
C765  0.1UF  [CAPC100X50X55]  131.46 73.93 90 bottom
C766  0.1UF  [CAPC100X50X55]  119.41 94.9 0 top
C767  0.1UF  [CAPC100X50X55]  121.35 75.1 180 bottom
C768  0.1UF  [CAPC100X50X55]  84.97 17 270 top
C769  0.1UF  [CAPC100X50X55]  84.12 17 270 top
C770  10UF  [CAPC100X50X70]  91.18 14.53 270 top
C771  1UF  [CAPC100X50X70]  92.07 14.53 270 top
C772  0.1UF  [CAPC100X50X55]  92.99 14.55 270 top
C773  0.1UF  [CAPC100X50X55]  88.84 14.97 270 top
C774  100PF  [CAPC100X50X55]  85.9 12.59 90 bottom
C775  100PF  [CAPC100X50X55]  84.47 11.13 180 bottom
C776  100PF  [CAPC100X50X55]  84.5 14.08 180 bottom
C777  0.1UF  [CAPC100X50X55]  80.66 16.88 270 top
C778  0.1UF  [CAPC100X50X55]  79.81 16.88 270 top
C779  100PF  [CAPC100X50X55]  96.69 13.89 270 bottom
C780  0.1UF  [CAPC100X50X55]  92.5 12.49 0 top
C781  100PF  [CAPC100X50X55]  98.04 15.41 0 bottom
C782  100PF  [CAPC100X50X55]  98.05 12.37 0 bottom
C783  0.1UF  [CAPC100X50X55]  104.8 14.55 90 top
C784  10UF  [CAPC620X540X280]  125.09 15.01 180 top
C785  0.1UF  [CAPC100X50X55]  67.03 12.82 0 bottom
C786  10UF  [CAPC100X50X70]  71.98 18.95 0 bottom
C787  10UF  [CAPC100X50X70]  73.98 18.95 180 bottom
C788  1000PF  [CAPC100X50X55]  75.94 16.63 270 bottom
C789  0.1UF  [CAPC100X50X55]  72.18 49.51 0 top
C793  0.1UF  [CAPC100X50X55]  75.58 53.32 180 top
C794  0.1UF  [CAPC100X50X55]  82.82 53.63 180 top
C795  0.1UF  [CAPC100X50X55]  75.58 62.27 180 top
C796  0.1UF  [CAPC100X50X55]  82.82 62.57 180 top
C797  0.1UF  [CAPC100X50X55]  75.58 71.21 180 top
C798  0.1UF  [CAPC100X50X55]  82.82 71.52 180 top
C799  0.1UF  [CAPC100X50X55]  75.58 44.38 180 top
C800  0.1UF  [CAPC100X50X55]  82.82 44.94 180 top
C801  0.1UF  [CAPC100X50X55]  123.35 64.31 180 bottom
C802  0.1UF  [CAPC100X50X55]  119.17 45.27 90 bottom
C803  0.1UF  [CAPC100X50X55]  72.18 57.38 0 top
C804  0.1UF  [CAPC100X50X55]  72.18 64.8 0 top
C805  0.1UF  [CAPC100X50X55]  71.98 40.67 0 top
C806  0.1UF  [CAPC100X50X55]  69.98 46.6 180 top
C807  0.1UF  [CAPC100X50X55]  69.98 54.48 180 top
C808  0.1UF  [CAPC100X50X55]  69.98 61.9 180 top
C809  0.1UF  [CAPC100X50X55]  69.78 37.77 180 top
C810  1000PF  [CAPC100X50X55]  65.99 46.21 0 top
C811  1000PF  [CAPC100X50X55]  65.99 47.35 0 top
C812  1000PF  [CAPC100X50X55]  65.99 42.96 0 top
C813  1000PF  [CAPC100X50X55]  65.99 41.82 0 top
C814  1000PF  [CAPC100X50X55]  65.99 54.38 0 top
C815  1000PF  [CAPC100X50X55]  65.99 55.52 0 top
C816  1000PF  [CAPC100X50X55]  65.99 51.13 0 top
C817  1000PF  [CAPC100X50X55]  65.99 49.99 0 top
C818  1000PF  [CAPC100X50X55]  65.99 62.55 0 top
C819  1000PF  [CAPC100X50X55]  65.99 63.69 0 top
C820  1000PF  [CAPC100X50X55]  65.99 59.3 0 top
C821  1000PF  [CAPC100X50X55]  65.99 58.15 0 top
C822  1000PF  [CAPC100X50X55]  65.99 38.04 0 top
C823  1000PF  [CAPC100X50X55]  65.99 39.19 0 top
C824  1000PF  [CAPC100X50X55]  65.99 34.79 0 top
C825  1000PF  [CAPC100X50X55]  65.99 33.65 0 top
C826  0.022uF  [CAPC100X50X55]  37.17 18.63 90 bottom
C827  0.022uF  [CAPC100X50X55]  44.24 18.59 90 bottom
C828  0.22UF  [CAPC100X50X55]  77.19 83.56 90 bottom
C829  0.22UF  [CAPC100X50X55]  63.62 30.04 0 bottom
D1  SMAJ16A  [DO_214AC]  21.74 99.46 0 top
D2  MMSD4148T1G  [SOD_123]  5.12 104.47 0 bottom
D3  MBRS260T3G  [DIO_SMB_403A_03]  100 38.68 90 top
D4  MBRS260T3G  [DIO_SMB_403A_03]  100 55.57 90 top
D5  MBRS260T3G  [DIO_SMB_403A_03]  99.23 70.68 90 top
D12  5.0SMDJ33A  [FUSE_LITTLEFUSE_50SMDJ_33A]  114.47 21 180 bottom
D15  RCLAMP0502BATCT  [SOT523_1C2C3A]  130.35 76.52 0 bottom
D16  RCLAMP0502BATCT  [SOT523_1C2C3A]  130.35 71.44 0 bottom
D17  RCLAMP0502BATCT  [SOT523_1C2C3A]  124.31 83.3 90 bottom
D18  RCLAMP0502BATCT  [SOT523_1C2C3A]  121.46 83.61 270 bottom
D19  RCLAMP0502BATCT  [SOT523_1C2C3A]  118.66 83.74 270 bottom
D20  RCLAMP0502BATCT  [SOT523_1C2C3A]  102.79 12.49 270 bottom
D21  TPD1E04U04DPYT  [DIOC100X60X45]  71.61 12.72 0 bottom
D22  SM712-02HTG  [SOT23_3]  125.98 86.59 180 top
D23  SM712-02HTG  [SOT23_3]  126.05 99.69 0 bottom
D24  -  [LED_0603]  38.19 18.75 270 top
D25  -  [LED_0603]  45.13 18.84 270 top
DS1  LED-GRN-SMT  [LED_0603]  2.97 29.26 0 top
DS2  LED-GRN-SMT  [LED_0603]  2.97 24.18 0 top
DS3  LED-GRN-SMT  [LED_0603]  2.97 21.64 0 top
DS4  LED-GRN-SMT  [LED_0603]  2.97 19.1 0 top
DS5  LED-GRN-SMT  [LED_0603]  2.97 16.56 0 top
DS6  LED-GRN-SMT  [LED_0603]  2.97 26.72 0 top
DS7  LED-GRN-SMT  [LED_0603]  2.97 36.88 0 top
DS8  LED-GRN-SMT  [LED_0603]  2.97 34.34 0 top
DS9  LED-GRN-SMT  [LED_0603]  135.68 16.56 0 top
DS10  LED-BLUE-SMT  [LED_0805]  134.03 38.09 0 top
F1  ITV5432  [FUSE_ITV5432L5030WR]  119.68 23.54 90 top
J1  -  [HDR_1X3]  38.88 21.95 0 top
J2  HDR_2X6_F_RA  [HDR_F2X6_PMOD]  18.55 10.31 0 top
J3  87832-1420  [87832_1420]  37.4 5.82 180 top
J4  ZX62D_AB_5P8(30)  [CON_HR_ZX62D_AB_5P8]  55.04 4.11 0 top
J11  -  [CON_MOL_10P_5025700893]  28.24 114.94 0 top
J12  PJ-202BH  [CON_CUI_PJ202AH]  16.68 104.54 90 top
J13  22-11-2022  [HDR_1X2_LOCK_MOLEX]  6.01 95.96 180 top
J15  BLACK  [TP_KEY_MINI]  22.9 92.54 0 top
J16  BLACK  [TP_KEY_MINI]  2.81 43.63 0 top
J17  BLACK  [TP_KEY_MINI]  76.46 27.56 0 top
J18  EM1935174  [PC_1935174]  122.16 112.5 180 top
J19  -  [HDR_1X3]  122.16 105.29 270 top
J20  -  [HDR_1X3]  117.08 105.29 270 top
J21  -  [HDR_1X3]  131.49 83.87 0 top
J22  18A  [CON_EUROMAG_ST_4_5MM]  132.63 90.72 180 top
J23  -  [HDR_1X2]  31.45 14.46 0 top
J24  RJ45  [CON_ETH_HFJ111G01E_L12RL]  72.23 111.29 180 top
J25  0879-2C1R-54  [BEL_0879-2C1R-54]  98.34 106.92 180 top
J26  BLACK  [TP_KEY_MINI]  103.24 43.39 0 top
J27  S2751-46R  [TP_SM_S2751R]  115.82 42.5 270 top
J28  BLACK  [TP_KEY_MINI]  103.3 60.29 0 top
J29  S2751-46R  [TP_SM_S2751R]  115.82 54.63 90 top
J30  BLACK  [TP_KEY_MINI]  102.44 75.73 0 top
J31  S2751-46R  [TP_SM_S2751R]  115.82 64.94 90 top
J32  MR60PB-M  [CON_AMASS_MR60PB-M]  133.09 45.51 90 top
J39  XT60PW-M  [AMASS_XT60PW-M]  125.42 24.26 270 top
J40  BLACK  [TP_KEY_MINI]  115.96 47.67 90 top
J41  BLACK  [TP_KEY_MINI]  119.16 30.27 180 top
J42  640456-6  [HDR_TE_1X6_100P]  135.12 65.86 270 top
J43  -  [HDR_2X5]  115.36 77.52 0 top
J44  -  [HDR_1X3]  91.19 72.22 270 top
J45  18A  [CON_EUROMAG_ST_4_5MM]  90.34 7.15 90 top
J46  EM1935174  [PC_1935174]  115.16 7.15 0 top
J47  EM1935174  [PC_1935174]  68.98 7.15 0 top
J51  -  [HDR_1X2]  31.45 18.32 0 top
J52  S2751-46R  [TP_SM_S2751R]  87.8 55.29 90 top
J53  S2751-46R  [TP_SM_S2751R]  87.8 63.67 90 top
J54  S2751-46R  [TP_SM_S2751R]  87.8 72.06 90 top
JA1  ADM6-60-01.5-L-4-2-A-TR  [CON_SAMTEC_ADM6_60_4]  14.74 60.23 270 top
JA3  ADM6-10-01.5-L-4-2-A-TR  [CON_SAMTEC_ADM6_10_4]  45.62 60.23 270 top
L1  1.2UH  [IND_COIL_XEL5030]  23.43 23.86 90 bottom
L2  FERRITE-600  [INDC200X125X110]  58.02 17.22 180 top
L3  FERRITE-600  [INDC200X125X110]  48.73 11.62 0 top
L4  FERRITE-220  [INDC160X80X95]  53.03 7.97 270 top
L5  FERRITE-220  [INDC160X80X95]  58.49 6.9 180 top
L8  FERRITE-600  [INDC160X80X95_MURATA]  6.58 101.67 180 bottom
L9  FERRITE-600  [INDC160X80X95_MURATA]  3.97 102.18 0 bottom
L10  BLM15EX331SN1D  [INDC_MURATA100X50X50]  114.14 95.92 0 top
L11  BLM15EX331SN1D  [INDC_MURATA100X50X50]  112.72 89.88 90 bottom
L12  BLM15EX331SN1D  [INDC_MURATA100X50X50]  112.55 80.19 270 top
L13  BLM15EX331SN1D  [INDC_MURATA100X50X50]  111.43 89.88 90 bottom
L14  BLM15EX331SN1D  [INDC_MURATA100X50X50]  111.27 80.68 270 top
L15  FERRITE-600  [INDC200X125X110]  69.67 97.26 180 top
L16  FERRITE-600  [INDC200X125X110]  108 88.31 180 bottom
L17  FERRITE-600  [INDC200X125X110]  107.62 92.25 180 top
MH1  -  [MH_NP_M3_SO_600]  135 5.01 0 top
MH2  -  [MH_NP_M3_SO_600]  135 113.98 0 top
MH3  -  [MH_NP_M3_SO_600]  5 114 0 top
MH4  -  [MH_NP_M3_SO_600]  5 5 0 top
MH5  -  [MH_C350HN350]  12.72 87.05 0 top
MH6  -  [MH_C350HN350]  83.37 87.05 0 top
MH7  -  [MH_C350HN350]  12.72 33.4 0 top
MH8  -  [MH_C350HN350]  83.37 33.4 0 top
MH9  -  [MH_C350HN350]  47.64 87.05 0 top
MH10  -  [MH_C350HN350]  47.64 33.4 0 top
NOREF  -  []  5 5 0 top
NOREF#2  -  [unnamed#2]  7.41 18.97 0 top
NOREF#3  -  []  361.36 372.66 0 top
NOREF#4  -  []  5 11.78 0 top
NOREF#5  -  []  12.72 33.4 0 top
NOREF#6  -  []  50.97 0.94 0 top
NOREF#7  -  []  57.32 4.24 0 top
NOREF#8  -  []  -13.64 72.63 0 top
NOREF#9  -  []  630.09 147.11 0 top
NOREF#10  -  []  71.93 113.9 0 top
NOREF#11  -  []  0 114.05 0 top
NOREF#12  -  []  16.94 110.54 0 top
NOREF#13  -  []  5 5 0 top
NOREF#14  -  [unnamed#2]  10.21 115.24 0 top
NOREF#15  -  []  5 5 0 top
NOREF#16  -  []  131.62 21 0 top
NOREF#17  -  []  108.56 -43.03 0 top
NOREF#18  -  []  -53.67 181.02 0 top
NOREF#19  -  []  18.42 104.74 0 top
NOREF#20  -  []  361.36 144.32 0 top
NOREF#21  -  []  5 4.62 0 top
NOREF#22  -  []  103.81 -58.6 0 top
NOREF#23  -  []  629.59 371.65 0 top
NOREF#24  -  []  4.62 5 0 top
NOREF#25  -  []  5 5 0 top
NOREF#26  -  []  5 5 0 top
NOREF#27  -  []  5 5 0 top
NOREF#28  -  []  5 5 0 top
NOREF#29  -  [unnamed#2]  127.98 115.45 0 top
NOREF#30  -  []  5 5 0 top
NOREF#31  -  []  606.98 -110.57 0 top
NOREF#32  -  [unnamed#2]  134.29 11.6 0 top
NOREF#33  -  []  83.37 33.4 90 top
NOREF#34  -  []  5 5 0 top
NOREF#35  -  []  30.27 114.01 0 top
NOREF#36  -  []  12.72 33.4 0 top
NOREF#37  -  []  20.24 22.4 0 top
NOREF#38  -  []  4.62 5 0 top
NOREF#39  -  []  8.5 114.4 0 top
NOREF#40  -  []  5 5 0 top
NOREF#41  -  []  135.05 0.01 90 top
NOREF#42  -  []  5 5 0 top
NOREF#43  -  []  12.11 107.62 0 top
NOREF#44  -  []  52.62 113.9 0 top
NOREF#45  -  []  5 5 0 top
NOREF#46  -  [unnamed#2]  10.33 115.24 180 bottom
NOREF#47  -  [unnamed#2]  127.94 115.11 180 bottom
NOREF#48  -  [unnamed#2]  134.07 11.61 180 bottom
NOREF#49  -  [unnamed#2]  7.29 18.84 180 bottom
Q5  IRFHS8342  [PQFN_65P210X2110X100-8]  13.61 95.9 90 top
Q6  DMN26D0UFB4-7  [DFN_105X65X40_3]  4.87 29.26 180 bottom
Q7  DMN26D0UFB4-7  [DFN_105X65X40_3]  4.67 24.18 180 bottom
Q8  DMN26D0UFB4-7  [DFN_105X65X40_3]  4.67 21.64 180 bottom
Q9  DMN26D0UFB4-7  [DFN_105X65X40_3]  4.67 19.1 180 bottom
Q10  DMN26D0UFB4-7  [DFN_105X65X40_3]  4.67 16.56 180 bottom
Q12  DMN26D0UFB4-7  [DFN_105X65X40_3]  53.67 19.1 180 top
Q13  DMN26D0UFB4-7  [DFN_105X65X40_3]  54.02 17.83 90 top
Q17  DMN26D0UFB4-7  [DFN_105X65X40_3]  4.67 26.72 180 bottom
Q18  NDS331N  [SOT_23]  6.01 107.51 90 bottom
Q19  DMN26D0UFB4-7  [DFN_105X65X40_3]  63.42 21.26 0 bottom
Q20  DMN26D0UFB4-7  [DFN_105X65X40_3]  2.68 107.23 0 bottom
Q21  DMN26D0UFB4-7  [DFN_105X65X40_3]  17.57 24.56 270 top
Q22  DMN26D0UFB4-7  [DFN_105X65X40_3]  4.67 36.88 180 bottom
Q23  DMN26D0UFB4-7  [DFN_105X65X40_3]  4.79 33.96 180 bottom
Q24  FDN304P  [SOT95P251X112-3]  77.54 21.97 90 bottom
Q25  FDN304P  [SOT95P251X112-3]  125.72 72.68 180 bottom
Q26  DMN26D0UFB4-7  [DFN_105X65X40_3]  70.78 22.36 0 bottom
Q27  DMN26D0UFB4-7  [DFN_105X65X40_3]  123.45 68.82 0 bottom
Q28  DMN26D0UFB4-7  [DFN_105X65X40_3]  133.91 15.54 0 bottom
Q29  DMN26D0UFB4-7  [DFN_105X65X40_3]  58.97 115.74 0 bottom
Q30  DMN26D0UFB4-7  [DFN_105X65X40_3]  84.45 110.93 90 bottom
Q31  DMN26D0UFB4-7  [DFN_105X65X40_3]  80.31 94.92 180 top
Q32  DMN26D0UFB4-7  [DFN_105X65X40_3]  106.47 84.63 0 top
Q33  DMN26D0UFB4-7  [DFN_105X65X40_3]  80.18 97.58 180 top
Q34  DMN26D0UFB4-7  [DFN_105X65X40_3]  106.47 81.96 0 top
Q35  CSD18512Q5B  [SON127P600X500X100-8TP]  111.1 31.95 270 top
Q36  CSD18512Q5B  [SON127P600X500X100-8TP]  111.1 41.22 270 top
Q37  DMN26D0UFB4-7  [DFN_105X65X40_3]  131.49 38.09 0 top
Q38  CSD18512Q5B  [SON127P600X500X100-8TP]  111.1 48.84 270 top
Q39  CSD18512Q5B  [SON127P600X500X100-8TP]  111.1 58.11 270 top
Q40  CSD18512Q5B  [SON127P600X500X100-8TP]  110.59 65.73 270 top
Q41  CSD18512Q5B  [SON127P600X500X100-8TP]  110.59 75 270 top
Q42  CSD18512Q5B  [SON127P600X500X100-8TP]  114.35 14.91 0 top
Q43  DMN26D0UFB4-7  [DFN_105X65X40_3]  113.33 40.23 90 bottom
Q44  DMN26D0UFB4-7  [DFN_105X65X40_3]  113.68 41.88 0 bottom
Q45  DMN26D0UFB4-7  [DFN_105X65X40_3]  39.71 18.5 0 bottom
Q46  DMN26D0UFB4-7  [DFN_105X65X40_3]  39.71 17.36 180 bottom
Q47  DMN26D0UFB4-7  [DFN_105X65X40_3]  46.78 18.59 0 bottom
Q48  DMN26D0UFB4-7  [DFN_105X65X40_3]  46.78 17.45 180 bottom
R1  200K  [RESC100X50X40]  8.12 56.13 270 bottom
R2  44.2K  [RESC100X50X40]  5.62 55.68 180 top
R4  100K  [RESC100X50X40]  6.98 51.48 0 bottom
R5  100K  [RESC100X50X40]  7.43 49.96 270 bottom
R6  8.06K  [RESC100X50X40]  67.59 75.26 270 bottom
R7  100K  [RESC100X50X40]  38.02 44.95 180 bottom
R14  68K  [RESC100X50X40]  32.81 82.72 270 bottom
R16  34.0K  [RESC100X50X40]  31.92 82.72 90 bottom
R17  10.0K  [RESC100X50X40]  67.14 73.1 180 bottom
R21  40.2K  [RESC100X50X40]  26.08 80.44 0 bottom
R23  10.0K  [RESC100X50X40]  56.46 30.65 0 bottom
R24  40.2K  [RESC100X50X40]  56.01 28.49 90 bottom
R26  40.2K  [RESC100X50X40]  26.08 79.55 180 bottom
R27  8.06K  [RESC100X50X40]  75.4 90.24 0 bottom
R28  100K  [RESC100X50X40]  38 43.97 180 bottom
R29  10.0K  [RESC100X50X40]  76.92 89.79 270 bottom
R30  20.0K  [RESC100X50X40]  16.57 19.04 90 bottom
R31  2.7K  [RESC100X50X40]  15.15 19.06 180 bottom
R32  1.00K  [RESC100X50X40]  17.59 20.39 180 bottom
R33  0  [RESC160X80X65]  19.75 19.39 270 bottom
R34  100K  [RESC60X30X26]  18.6 19.04 90 bottom
R36  56.2K  [RESC100X50X40]  38.5 14.57 180 bottom
R38  10.0K  [RESC100X50X40]  5.41 40.61 180 bottom
R39  56.2K  [RESC100X50X40]  7.19 39.59 180 bottom
R40  10.0K  [RESC100X50X40]  41.64 16.65 180 top
R41  10.0K  [RESC100X50X40]  38.05 16.04 90 bottom
R44  0  [RESC100X50X40]  18.84 40.81 0 bottom
R45  10.0K  [RESC100X50X40]  38.82 25.19 180 bottom
R46  10.0K  [RESC100X50X40]  1.68 91.11 270 bottom
R47  10.0K  [RESC100X50X40]  3.65 83.54 90 bottom
R48  10.0K  [RESC100X50X40]  5.43 83.54 90 bottom
R49  10.0K  [RESC100X50X40]  2.76 83.54 90 bottom
R50  10.0K  [RESC100X50X40]  2.64 91.11 90 bottom
R51  10.0K  [RESC100X50X40]  4.54 83.54 270 bottom
R54  200K  [RESC100X50X40]  29.27 21.31 90 top
R55  2.21K  [RESC100X50X40]  28.5 23.6 270 bottom
R56  2.21K  [RESC100X50X40]  27.61 23.6 270 bottom
R58  1.50K  [RESC100X50X40]  84.43 49.12 180 bottom
R61  1.50K  [RESC100X50X40]  84.43 55.2 180 bottom
R63  1.50K  [RESC100X50X40]  77.19 48.82 180 bottom
R64  1.50K  [RESC100X50X40]  77.19 54.89 180 bottom
R66  0  [RESC100X50X40]  38.53 31.72 90 bottom
R74  10.0K  [RESC100X50X40]  65.03 15.35 90 top
R75  1.00K  [RESC100X50X40]  52.36 12.13 270 top
R76  10.0K  [RESC100X50X40]  67.57 15.35 270 top
R77  10.0K  [RESC100X50X40]  68.84 15.35 270 top
R78  2.00K  [RESC100X50X40]  66.3 15.35 270 top
R79  12.0K  [RESC100X50X40]  56.31 12.07 90 top
R130  100K  [RESC100X50X40]  36.22 93.68 180 bottom
R133  300K  [RESC100X50X40]  16.18 95.17 270 bottom
R134  274K  [RESC100X50X40]  15.51 98.95 90 bottom
R135  422  [RESC100X50X40]  16.4 98.95 90 top
R157  261  [RESC100X50X40]  2.89 29.26 180 bottom
R158  261  [RESC100X50X40]  2.89 24.18 180 bottom
R159  261  [RESC100X50X40]  2.89 21.64 180 bottom
R160  261  [RESC100X50X40]  2.89 19.1 180 bottom
R161  261  [RESC100X50X40]  2.89 16.56 180 bottom
R162  499  [RESC100X50X40]  20.11 61.51 0 bottom
R163  499  [RESC100X50X40]  20.11 60.24 0 bottom
R164  499  [RESC100X50X40]  20.11 58.97 0 bottom
R165  499  [RESC100X50X40]  20.11 57.7 0 bottom
R166  100K  [RESC100X50X40]  6.14 10.97 270 bottom
R167  10.0K  [RESC100X50X40]  6.14 14.52 270 bottom
R209  10.0K  [RESC100X50X40]  48.88 75.69 180 bottom
R210  10.0K  [RESC100X50X40]  44.2 72.04 90 bottom
R213  8.06K  [RESC100X50X40]  48.88 74.81 0 bottom
R218  10.0K  [RESC100X50X40]  70.58 86.88 180 bottom
R219  200K  [RESC100X50X40]  70.58 89.42 0 bottom
R220  200K  [RESC100X50X40]  70.58 87.9 0 bottom
R221  12.0K  [RESC100X50X40]  58.44 87.57 180 bottom
R222  0  [RESC100X50X40]  62 84.4 270 bottom
R223  1.00  [RESC200X125X75]  24.32 18.94 0 bottom
R233  10.0K  [RESC100X50X40]  53.77 20.11 180 top
R234  10.0K  [RESC100X50X40]  56.05 20.11 0 top
R235  10.0K  [RESC100X50X40]  54.2 16.47 180 top
R241  10.0K  [RESC100X50X40]  37.35 25.43 270 bottom
R243  10.0K  [RESC100X50X40]  60.43 74.96 270 bottom
R248  30  [RESC100X50X40]  27.49 100.58 180 bottom
R249  30  [RESC100X50X40]  26.06 98.71 180 bottom
R250  30  [RESC100X50X40]  25.67 96.71 180 bottom
R251  30  [RESC100X50X40]  25.67 95.7 180 bottom
R252  30  [RESC100X50X40]  36.22 94.83 0 bottom
R253  30  [RESC100X50X40]  36.22 95.97 0 bottom
R254  261  [RESC100X50X40]  2.89 26.72 180 bottom
R256  1.00K  [RESC100X50X40]  34.5 26.95 270 top
R260  10.0K  [RESC100X50X40]  2.68 108.5 0 bottom
R261  10.0K  [RESC100X50X40]  2.68 106.08 0 bottom
R262  10.0K  [RESC100X50X40]  62.74 19.51 270 bottom
R263  10.0K  [RESC100X50X40]  9.7 61.64 180 bottom
R264  20  [RESC100X50X40]  19.35 56.18 0 bottom
R265  100K  [RESC60X30X26]  17.57 25.7 180 top
R266  100.0K  [RESC100X50X40]  40.1 17.99 270 top
R267  100.0K  [RESC100X50X40]  38.19 18.5 270 bottom
R274  20  [RESC100X50X40]  25.76 16.18 270 top
R275  20  [RESC100X50X40]  29 11.41 180 bottom
R276  0  [RESC100X50X40]  10.59 50.08 180 bottom
R277  0  [RESC100X50X40]  10.59 51.23 180 bottom
R278  0  [RESC100X50X40]  10.59 52.24 180 bottom
R279  0  [RESC100X50X40]  10.59 53.39 180 bottom
R280  0  [RESC100X50X40]  10.59 55.55 180 bottom
R281  0  [RESC100X50X40]  10.59 54.53 180 bottom
R282  0  [RESC100X50X40]  10.59 56.82 180 bottom
R283  0  [RESC100X50X40]  10.59 58.09 180 bottom
R294  261  [RESC100X50X40]  2.89 36.88 180 bottom
R295  261  [RESC100X50X40]  2.89 34.34 180 bottom
R428  12.0K  [RESC100X50X40]  27.78 91.59 270 bottom
R429  10.0K  [RESC100X50X40]  34.03 100.54 180 bottom
R446  4.70K  [RESC100X50X40]  38.25 42.18 180 bottom
R447  4.70K  [RESC100X50X40]  34.2 45.93 270 bottom
R448  4.70K  [RESC100X50X40]  33.31 45.93 270 bottom
R449  4.70K  [RESC100X50X40]  32.13 37.57 90 bottom
R450  4.70K  [RESC100X50X40]  33.02 37.56 90 bottom
R451  4.70K  [RESC100X50X40]  33.89 37.56 90 bottom
R452  30  [RESC100X50X40]  35.08 45.93 270 bottom
R462  2.21K  [RESC100X50X40]  32.41 110.47 0 bottom
R463  10.0K  [RESC100X50X40]  36.22 92.54 180 bottom
R464  10.0K  [RESC100X50X40]  34.99 91.37 180 bottom
R465  4.70K  [RESC100X50X40]  32.42 93.92 180 top
R466  1.0M  [RESC100X50X40]  30.63 91.75 0 bottom
R467  1.0M  [RESC100X50X40]  47.51 72.52 0 bottom
R468  10.0K  [RESC100X50X40]  65.05 97.35 90 bottom
R469  10.0K  [RESC100X50X40]  65.94 97.35 90 bottom
R471  10.0K  [RESC100X50X40]  75.7 83.08 0 bottom
R472  10.0K  [RESC100X50X40]  63.18 28.79 90 bottom
R473  100K  [RESC100X50X40]  6.14 37.64 90 bottom
R474  100K  [RESC100X50X40]  5 35.61 180 bottom
R477  0  [RESC100X50X40]  69.65 80.98 180 bottom
R478  0  [RESC100X50X40]  79.81 79.21 0 bottom
R479  0  [RESC100X50X40]  79.56 81.11 0 bottom
R480  0  [RESC100X50X40]  79.81 80.33 0 bottom
R494  4.70K  [RESC100X50X40]  1.84 65.32 270 bottom
R495  499  [RESC100X50X40]  7.96 66.79 90 bottom
R500  4.70K  [RESC100X50X40]  63.52 80.24 90 bottom
R501  0  [RESC100X50X40]  69.63 79.16 0 bottom
R507  4.70K  [RESC100X50X40]  69.66 80.12 0 bottom
R514  100K  [RESC100X50X40]  107.51 99.73 0 bottom
R515  10.0K  [RESC100X50X40]  113.37 107.36 0 bottom
R516  10.0K  [RESC100X50X40]  107.51 101 180 bottom
R517  60.4  [RESC100X50X40]  119.62 102.12 270 bottom
R518  60.4  [RESC100X50X40]  119.62 104.02 90 bottom
R519  10.0K  [RESC100X50X40]  114.46 93.17 180 bottom
R520  120  [RESC200X125X50]  127.03 84.86 90 bottom
R521  10.0K  [RESC100X50X40]  51.56 75.64 270 bottom
R522  26.1K  [RESC100X50X40]  58.72 75.94 270 bottom
R523  10.0K  [RESC100X50X40]  58.28 74.22 180 bottom
R524  73.2K  [RESC100X50X40]  67.52 26.39 270 top
R525  16.2K  [RESC100X50X40]  68.66 26.77 90 top
R526  10.0K  [RESC100X50X40]  74.46 23 180 bottom
R527  10.0K  [RESC100X50X40]  124.7 69.6 270 bottom
R528  10.0K  [RESC100X50X40]  74.46 21.94 0 bottom
R529  10.0K  [RESC100X50X40]  125.75 69.6 90 bottom
R530  4.70K  [RESC100X50X40]  38.01 43.09 180 bottom
R531  40.2K  [RESC100X50X40]  132.25 13.76 90 bottom
R532  10.0K  [RESC100X50X40]  132.25 15.54 90 bottom
R533  261  [RESC100X50X40]  135.05 15.99 90 bottom
R534  0  [RESC100X50X40]  114.01 83.58 270 bottom
R536  1.50K  [RESC100X50X40]  55.4 97.53 270 top
R537  1.50K  [RESC100X50X40]  57.31 95.45 0 top
R538  1.00K  [RESC100X50X40]  70.58 91.84 180 top
R539  3.01K  [RESC100X50X40]  70.58 94.88 0 bottom
R540  1.0M  [RESC100X50X40]  69.85 94.27 90 top
R541  10.0K  [RESC100X50X40]  61.52 82.21 0 top
R542  10.0K  [RESC100X50X40]  54.84 89.31 0 top
R543  10.0K  [RESC100X50X40]  54.84 88.42 0 top
R544  10.0K  [RESC100X50X40]  58.9 85.41 90 top
R545  10.0K  [RESC100X50X40]  60.6 84.16 0 top
R546  10.0K  [RESC100X50X40]  54.84 91.97 0 top
R547  10.0K  [RESC100X50X40]  60.11 82.38 90 top
R548  10.0K  [RESC100X50X40]  54.84 92.86 0 top
R549  10.0K  [RESC100X50X40]  57.28 96.89 0 top
R550  0  [RESC100X50X40]  59.74 114.6 0 bottom
R551  261  [RESC100X50X40]  60.63 115.74 0 bottom
R552  10.0K  [RESC100X50X40]  62.38 84.39 270 top
R553  10.0K  [RESC100X50X40]  54.84 90.2 180 top
R554  10.0K  [RESC100X50X40]  54.84 87.53 180 top
R555  10.0K  [RESC100X50X40]  57.89 85.41 270 top
R556  10.0K  [RESC100X50X40]  60.6 85.17 180 top
R557  10.0K  [RESC100X50X40]  54.84 91.09 180 top
R558  10.0K  [RESC100X50X40]  59.1 82.38 270 top
R559  10.0K  [RESC100X50X40]  54.84 93.75 180 top
R560  10.0K  [RESC100X50X40]  57.28 96.89 180 bottom
R561  261  [RESC100X50X40]  83.15 112.12 90 bottom
R563  1.50K  [RESC100X50X40]  102.66 88.95 180 bottom
R564  1.50K  [RESC100X50X40]  102.66 89.84 180 bottom
R565  1.00K  [RESC100X50X40]  90.6 88.06 0 bottom
R566  3.01K  [RESC100X50X40]  90.6 89.2 180 bottom
R567  0  [RESC100X50X40]  80.31 93.9 180 top
R568  10.0K  [RESC100X50X40]  97.2 80.54 90 bottom
R569  10.0K  [RESC100X50X40]  102.66 82.72 180 bottom
R570  10.0K  [RESC100X50X40]  103.04 80.82 180 bottom
R571  10.0K  [RESC100X50X40]  102.02 78.7 180 bottom
R572  10.0K  [RESC100X50X40]  99.61 80.54 90 bottom
R573  10.0K  [RESC100X50X40]  102.66 84.5 180 bottom
R574  10.0K  [RESC100X50X40]  98.22 80.54 90 bottom
R575  10.0K  [RESC100X50X40]  102.66 87.17 180 bottom
R576  10.0K  [RESC100X50X40]  103.04 91.74 180 bottom
R577  261  [RESC100X50X40]  78.66 94.92 180 top
R578  261  [RESC100X50X40]  108.12 84.63 0 top
R579  2.21K  [RESC100X50X40]  57.38 71.67 0 top
R580  2.21K  [RESC100X50X40]  57.4 72.68 0 top
R581  1.00K  [RESC100X50X40]  57.4 70.6 180 top
R582  10.0K  [RESC100X50X40]  97.2 78.25 270 bottom
R583  10.0K  [RESC100X50X40]  103.98 81.81 0 bottom
R584  10.0K  [RESC100X50X40]  103.02 79.7 180 bottom
R585  10.0K  [RESC100X50X40]  100.63 78.25 270 bottom
R586  10.0K  [RESC100X50X40]  99.61 78.25 270 bottom
R587  10.0K  [RESC100X50X40]  102.66 85.39 0 bottom
R588  10.0K  [RESC100X50X40]  98.22 78.25 90 bottom
R589  10.0K  [RESC100X50X40]  102.79 86.15 0 bottom
R590  10.0K  [RESC100X50X40]  102.66 90.72 0 bottom
R592  1.50K  [RESC100X50X40]  90.6 89.2 0 top
R593  1.50K  [RESC100X50X40]  90.6 90.09 0 top
R594  1.00K  [RESC100X50X40]  102.66 88.06 180 top
R595  3.01K  [RESC100X50X40]  102.66 89.84 0 top
R596  0  [RESC100X50X40]  80.18 96.57 180 top
R597  10.0K  [RESC100X50X40]  97.2 80.56 90 top
R598  10.0K  [RESC100X50X40]  90.6 82.47 0 top
R599  10.0K  [RESC100X50X40]  90.6 79.68 0 top
R600  10.0K  [RESC100X50X40]  94.15 80.54 90 top
R601  10.0K  [RESC100X50X40]  96.19 80.54 90 top
R602  10.0K  [RESC100X50X40]  90.6 86.28 0 top
R603  10.0K  [RESC100X50X40]  95.17 80.54 90 top
R604  10.0K  [RESC100X50X40]  90.6 84.5 0 top
R605  10.0K  [RESC100X50X40]  90.6 90.98 0 top
R606  261  [RESC100X50X40]  78.53 97.58 180 top
R607  261  [RESC100X50X40]  108.12 81.96 0 top
R608  10.0K  [RESC100X50X40]  97.2 78.25 270 top
R609  10.0K  [RESC100X50X40]  90.6 81.45 180 top
R610  10.0K  [RESC100X50X40]  90.6 80.56 180 top
R611  10.0K  [RESC100X50X40]  94.15 78.25 270 top
R612  10.0K  [RESC100X50X40]  95.17 78.25 270 top
R613  10.0K  [RESC100X50X40]  90.6 85.39 180 top
R614  10.0K  [RESC100X50X40]  96.19 78.25 270 top
R615  10.0K  [RESC100X50X40]  90.6 87.17 180 top
R616  10.0K  [RESC100X50X40]  90.6 91.87 180 top
R617  2.2  [RESC320X160X70]  100 38.68 90 bottom
R618  0  [RESC100X50X40]  106.85 41.96 270 bottom
R619  4.7  [RESC100X50X40]  107.05 34.8 0 bottom
R620  0  [RESC100X50X40]  107.41 39.42 90 bottom
R621  4.7  [RESC100X50X40]  106.85 43.98 0 top
R622  2.21K  [RESC100X50X40]  134.36 38.09 0 bottom
R623  10.0K  [RESC100X50X40]  108.25 39.43 270 bottom
R624  10.0K  [RESC100X50X40]  106.85 41.96 90 top
R625  20.0K  [RESC100X50X40]  107.74 41.96 90 top
R626  2.2  [RESC320X160X70]  100 55.57 90 bottom
R627  0  [RESC100X50X40]  106.85 58.85 270 bottom
R628  4.7  [RESC100X50X40]  107.05 51.69 0 bottom
R629  4.7  [RESC100X50X40]  106.87 61.15 0 top
R630  10.0K  [RESC100X50X40]  106.85 58.85 90 top
R631  20.0K  [RESC100X50X40]  107.74 58.85 90 top
R632  2.2  [RESC320X160X70]  99.23 70.68 90 bottom
R633  0  [RESC100X50X40]  106.35 75.74 270 bottom
R634  4.7  [RESC100X50X40]  106.54 68.59 0 bottom
R635  4.7  [RESC100X50X40]  106.35 77.76 0 top
R636  10.0K  [RESC100X50X40]  106.35 75.74 90 top
R637  20.0K  [RESC100X50X40]  107.23 75.74 90 top
R638  0.002  [RESC640X320X70]  123.44 42.34 0 top
R639  0.002  [RESC640X320X70]  123.57 52.37 0 top
R640  0.002  [RESC640X320X70]  123.57 61.39 0 top
R641  25.5K  [RESC100X50X35]  126.86 45.95 180 bottom
R642  1.5K  [RESC100X50X40]  126.04 44.01 180 bottom
R643  20  [RESC100X50X40]  126.49 42.54 270 bottom
R646  20  [RESC100X50X40]  119.85 37 180 bottom
R647  25.5K  [RESC100X50X35]  117.94 56.29 90 bottom
R648  1.5K  [RESC100X50X40]  119.53 59.14 0 bottom
R649  20  [RESC100X50X40]  119.08 60.6 90 bottom
R650  20  [RESC100X50X40]  120.7 47.42 90 bottom
R651  25.5K  [RESC100X50X35]  132.79 63.62 180 bottom
R652  1.5K  [RESC100X50X40]  129.77 63.62 180 bottom
R653  20  [RESC100X50X40]  130.22 62.15 270 bottom
R656  20  [RESC100X50X40]  119.55 56.43 180 bottom
R659  0.002  [RESC640X320X70]  112.19 22.91 180 top
R660  25.5K  [RESC100X50X35]  114.87 44.95 0 bottom
R661  1.5K  [RESC100X50X40]  115.72 42.88 0 bottom
R662  20  [RESC100X50X40]  115.02 41.43 270 bottom
R663  20  [RESC100X50X40]  115.63 28.75 90 bottom
R664  2.21K  [RESC100X50X40]  129.82 70.94 180 top
R665  2.21K  [RESC100X50X40]  129.82 71.94 180 top
R666  2.21K  [RESC100X50X40]  130.09 77.01 180 top
R667  10.0K  [RESC100X50X40]  117.33 96.25 270 top
R668  2.21K  [RESC100X50X40]  116.31 96.25 90 top
R669  100  [RESC100X50X40]  121.46 85.77 0 bottom
R670  100  [RESC100X50X40]  124.32 85.7 180 bottom
R671  100  [RESC100X50X40]  118.66 86.03 0 bottom
R672  10.0K  [RESC100X50X40]  126.81 93.26 180 bottom
R673  0  [RESC100X50X40]  84.5 12.08 0 bottom
R674  0  [RESC100X50X40]  86.91 12.59 90 bottom
R675  0  [RESC100X50X40]  84.5 13.1 0 bottom
R676  0  [RESC100X50X40]  98.04 14.34 180 bottom
R677  0  [RESC100X50X40]  98.05 13.44 180 bottom
R678  10  [RESC100X50X40]  108.53 12.76 0 top
R679  10.0K  [RESC100X50X40]  106.67 12.76 180 top
R680  4.70K  [RESC100X50X40]  69.47 12.72 0 bottom
R681  10.0K  [RESC100X50X40]  115.25 90.14 270 bottom
R682  10.0K  [RESC100X50X40]  121.43 95.43 180 top
R683  10.0K  [RESC100X50X40]  116.86 90.18 270 bottom
R684  80.6K  [RESC100X50X40]  76.96 16.63 270 bottom
R685  10.0K  [RESC100X50X40]  76.51 14.47 180 bottom
R702  3.01K  [RESC100X50X40]  73.62 49.99 90 bottom
R703  3.01K  [RESC100X50X40]  73.62 53.74 270 bottom
R704  3.01K  [RESC100X50X40]  80.85 50.3 90 bottom
R705  3.01K  [RESC100X50X40]  80.85 54.05 270 bottom
R706  3.01K  [RESC100X50X40]  73.62 58.94 90 bottom
R707  1.50K  [RESC100X50X40]  77.19 57.77 180 bottom
R708  1.50K  [RESC100X50X40]  77.19 63.84 180 bottom
R709  3.01K  [RESC100X50X40]  73.62 62.69 270 bottom
R710  3.01K  [RESC100X50X40]  80.85 59.24 90 bottom
R711  1.50K  [RESC100X50X40]  84.43 58.07 180 bottom
R712  1.50K  [RESC100X50X40]  84.43 64.15 180 bottom
R713  3.01K  [RESC100X50X40]  80.85 62.99 270 bottom
R714  3.01K  [RESC100X50X40]  73.62 67.89 90 bottom
R715  1.50K  [RESC100X50X40]  77.19 66.71 180 bottom
R716  1.50K  [RESC100X50X40]  77.19 72.79 180 bottom
R717  3.01K  [RESC100X50X40]  73.62 71.64 270 bottom
R718  3.01K  [RESC100X50X40]  80.85 68.19 90 bottom
R719  1.50K  [RESC100X50X40]  84.43 67.02 180 bottom
R720  1.50K  [RESC100X50X40]  84.43 73.09 180 bottom
R721  3.01K  [RESC100X50X40]  80.85 71.94 270 bottom
R722  3.01K  [RESC100X50X40]  73.62 41.05 90 bottom
R723  1.50K  [RESC100X50X40]  77.19 39.87 180 bottom
R724  1.50K  [RESC100X50X40]  77.19 45.95 180 bottom
R725  3.01K  [RESC100X50X40]  73.62 44.8 270 bottom
